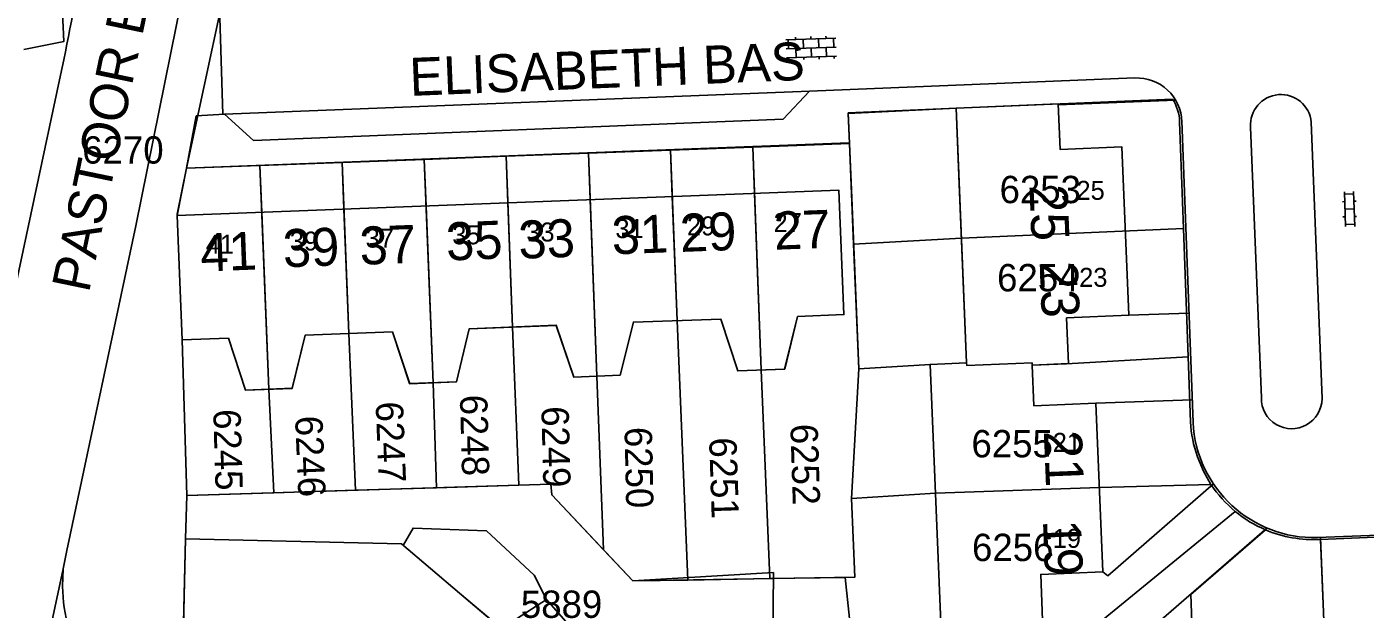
# Model space of a CAD drawing. Extents: x 148816 to 151297, y 399515 to 402500.
# Drawn here: x 150122.1 to 150210.2, y 399895.9 to 399934.3 of the extents above; entities that cross this region are included whole.
import ezdxf

# ---------------------------------------------------------------- set-up
doc = ezdxf.new("R2010")
doc.units = 0
for name, color, linetype in [('B01 Hoofdgebouw  [D] Norm', 7, 'Continuous'), ('B01 Hoofdgebouw  [T] Norm', 7, 'Continuous'), ('B01 hoofgebouw', 7, 'Continuous'), ('B07 Tussenmuur  [D] Norm', 7, 'Continuous'), ('G01 perceelsgrens', 7, 'Continuous'), ('S02 Open verharding  Norm', 7, 'Continuous'), ('T01 Muur  [T] Gem', 7, 'Continuous'), ('T04 Haag heg  [D] Gem', 7, 'Continuous'), ('V00 Kant verharding algemeen  [T] Norm', 7, 'Continuous'), ('V00 Kant verharding algemeen secundair  [T] Gem', 7, 'Continuous'), ('Z01 perceelnummer', 7, 'Continuous'), ('Z02 huisnummer', 7, 'Continuous'), ('Z02 Huisnummer  [Tekst] Norm', 7, 'Continuous'), ('Z06 straatnaam', 7, 'Continuous')]:
    doc.layers.add(name, color=color, linetype=linetype)

msp = doc.modelspace()

# ---------------------------------------------------------------- linework, layer by layer
at = {"layer": 'B01 Hoofdgebouw  [D] Norm'}
for p, q in [((150183.96, 399912.15), (150183.966, 399911.981)), ((150183.966, 399911.981), (150188.264, 399912.148)), ((150188.264, 399912.148), (150188.273, 399911.998)), ((150162.01, 399897.79), (150171.252, 399898.342)), ((150171.252, 399898.342), (150171.219, 399893.637))]:
    msp.add_line(p, q, dxfattribs=at)
msp.add_lwpolyline([(150150.6, 399896.99), (150153.353, 399894.649), (150156.332, 399896.578), (150158.387, 399894.21)], dxfattribs=at)
at = {"layer": 'B01 Hoofdgebouw  [T] Norm'}
for p, q in [((150189.977, 399929.201), (150183.275, 399928.921)), ((150183.275, 399928.921), (150183.955, 399912.147)), ((150190.106, 399926.201), (150189.977, 399929.201)), ((150194.177, 399926.366), (150190.106, 399926.201)), ((150194.177, 399926.366), (150194.622, 399915.28)), ((150132.028, 399921.849), (150175.555, 399923.514)), ((150175.555, 399923.514), (150175.889, 399915.323)), ((150132.028, 399921.849), (150132.362, 399913.658)), ((150172.841, 399915.211), (150171.988, 399911.738)), ((150175.889, 399915.323), (150172.841, 399915.211)), ((150194.622, 399915.28), (150190.539, 399915.105)), ((150190.539, 399915.105), (150190.66, 399912.1)), ((150168.901, 399911.62), (150171.988, 399911.738)), ((150183.955, 399912.147), (150181.559, 399912.051)), ((150181.559, 399912.051), (150182.265, 399895.028)), ((150190.66, 399912.1), (150188.273, 399911.998)), ((150188.273, 399911.998), (150188.381, 399909.325)), ((150158.115, 399911.214), (150161.18, 399911.338)), ((150188.381, 399909.325), (150192.468, 399909.49)), ((150192.468, 399909.49), (150192.916, 399898.386)), ((150156.61, 399904.16), (150132.66, 399903.41)), ((150156.67, 399903.46), (150156.61, 399904.16)), ((150162.01, 399897.79), (150156.67, 399903.46)), ((150132.36, 399891.36), (150132.58, 399900.56)), ((150132.58, 399900.56), (150146.79, 399900.23)), ((150146.79, 399900.23), (150150.6, 399896.99)), ((150188.829, 399898.221), (150192.916, 399898.386)), ((150188.951, 399895.211), (150188.829, 399898.221))]:
    msp.add_line(p, q, dxfattribs=at)
for points in [[(150176.174, 399928.622), (150183.282, 399928.928)], [(150158.115, 399911.214), (150156.966, 399914.621), (150151.238, 399914.399), (150150.399, 399910.903)], [(150168.901, 399911.62), (150167.786, 399915.032), (150162.043, 399914.832), (150161.18, 399911.338)], [(150132.362, 399913.658), (150135.396, 399913.771), (150136.515, 399910.355), (150139.595, 399910.474)], [(150146.188, 399914.186), (150140.449, 399913.969), (150139.595, 399910.474)], [(150146.188, 399914.186), (150147.324, 399910.775), (150150.399, 399910.903)]]:
    msp.add_lwpolyline(points, dxfattribs=at)
at = {"layer": 'B01 hoofgebouw'}
for points in [[(150183.477, 399923.926), (150183.275, 399928.921), (150189.977, 399929.201), (150190.106, 399926.201), (150194.177, 399926.366), (150194.622, 399915.28), (150190.539, 399915.105), (150190.66, 399912.1), (150188.273, 399911.998), (150188.381, 399909.325), (150192.468, 399909.49), (150192.916, 399898.386), (150188.829, 399898.221), (150188.951, 399895.211), (150183.31, 399894.982), (150183.436, 399891.87), (150184.179, 399891.87), (150184.526, 399882.723), (150179.53, 399882.533)], [(150135.396, 399913.771), (150132.362, 399913.658), (150132.028, 399921.849), (150175.555, 399923.514), (150175.889, 399915.323), (150172.841, 399915.211)], [(150183.477, 399923.926), (150183.96, 399912.15), (150181.56, 399912.05), (150182.27, 399895.03), (150176.73, 399894.8), (150176.86, 399891.6)], [(150135.4, 399913.77), (150136.52, 399910.36), (150139.6, 399910.47), (150140.45, 399913.97), (150146.19, 399914.19), (150147.32, 399910.78), (150150.4, 399910.9), (150151.24, 399914.4), (150156.97, 399914.62), (150158.12, 399911.21), (150161.18, 399911.34), (150162.04, 399914.83), (150167.79, 399915.03), (150168.9, 399911.62), (150171.99, 399911.74), (150172.84, 399915.21)], [(150177.38, 399858.38), (150174.27, 399854.46), (150157.39, 399867.87), (150146.1, 399877.88), (150146.2, 399877.97), (150141.11, 399882.58), (150141.04, 399882.49), (150134.15, 399888.76), (150134.23, 399888.84), (150132.93, 399889.99), (150132.82, 399889.97), (150132.27, 399891.31), (150132.36, 399891.36), (150132.58, 399900.56), (150146.79, 399900.23), (150150.6, 399896.99)], [(150150.6, 399896.99), (150152.767, 399895.147)]]:
    msp.add_lwpolyline(points, dxfattribs=at)
at = {"layer": 'B07 Tussenmuur  [D] Norm'}
for p, q in [((150170.451, 399911.68), (150170.003, 399923.302)), ((150170.451, 399911.68), (150170.003, 399923.302)), ((150143.312, 399914.08), (150142.993, 399922.268)), ((150143.312, 399914.08), (150142.993, 399922.268)), ((150148.861, 399910.84), (150148.399, 399922.475)), ((150148.861, 399910.84), (150148.399, 399922.475)), ((150154.092, 399914.51), (150153.785, 399922.681)), ((150154.092, 399914.51), (150153.785, 399922.681)), ((150159.641, 399911.275), (150159.2, 399922.888)), ((150159.641, 399911.275), (150159.2, 399922.888)), ((150164.912, 399914.93), (150164.597, 399923.095)), ((150164.912, 399914.93), (150164.597, 399923.095)), ((150137.597, 399922.062), (150138.061, 399910.415)), ((150137.597, 399922.062), (150138.061, 399910.415)), ((150183.627, 399920.357), (150198.227, 399920.989)), ((150183.627, 399920.357), (150198.227, 399920.989)), ((150181.913, 399903.577), (150192.695, 399903.935)), ((150181.913, 399903.577), (150192.695, 399903.935))]:
    msp.add_line(p, q, dxfattribs=at)
at = {"layer": 'G01 perceelsgrens'}
for points in [[(150120.655, 399953.937), (150123.589, 399954.459), (150124.564, 399933.301), (150121.954, 399932.791)], [(150132.645, 399924.965), (150136.128, 399941.229)], [(150197.5, 399929.52), (150183.28, 399928.92), (150176.174, 399928.576), (150176.255, 399926.588)], [(150197.97, 399928.03), (150198.227, 399920.989)], [(150153.669, 399925.748), (150159.084, 399925.949)], [(150159.084, 399925.949), (150164.48, 399926.15)], [(150159.084, 399925.949), (150159.641, 399911.275), (150160.073, 399899.847)], [(150164.48, 399926.15), (150169.886, 399926.351)], [(150164.48, 399926.15), (150164.912, 399914.93), (150165.612, 399897.85)], [(150169.886, 399926.351), (150176.255, 399926.588)], [(150169.886, 399926.351), (150170.451, 399911.68), (150171.012, 399897.941)], [(150176.255, 399926.588), (150176.526, 399919.963)], [(150132.645, 399924.965), (150132.03, 399921.85), (150132.36, 399913.66), (150132.66, 399903.41)], [(150132.645, 399924.965), (150137.474, 399925.145)], [(150137.474, 399925.145), (150142.873, 399925.346)], [(150137.474, 399925.145), (150138.061, 399910.415), (150138.379, 399903.589)], [(150142.873, 399925.346), (150148.276, 399925.547)], [(150142.873, 399925.346), (150143.312, 399914.08), (150143.75, 399903.757)], [(150148.276, 399925.547), (150153.669, 399925.748)], [(150148.276, 399925.547), (150148.861, 399910.84), (150149.097, 399903.925)], [(150153.669, 399925.748), (150154.092, 399914.51), (150154.512, 399904.094)], [(150176.526, 399919.963), (150183.627, 399920.357), (150198.227, 399920.989)], [(150198.227, 399920.989), (150198.535, 399912.54)], [(150176.526, 399919.963), (150176.861, 399911.747)], [(150176.387, 399903.217), (150176.861, 399911.747)], [(150176.861, 399911.747), (150181.56, 399912.05), (150183.96, 399912.15), (150183.966, 399911.981), (150188.264, 399912.148), (150188.27, 399912), (150190.53, 399912.095), (150198.535, 399912.54)], [(150198.535, 399912.54), (150198.69, 399908.27)], [(150199.14, 399905.96), (150199.531, 399905.029), (150200.03, 399904.15)], [(150138.379, 399903.589), (150143.75, 399903.757)], [(150143.75, 399903.757), (150149.097, 399903.925)], [(150149.097, 399903.925), (150154.512, 399904.094)], [(150154.512, 399904.094), (150156.61, 399904.16), (150156.67, 399903.46), (150160.073, 399899.847)], [(150176.387, 399903.217), (150181.913, 399903.577), (150192.695, 399903.935), (150200.03, 399904.15)], [(150132.733, 399886.712), (150132.249, 399889.719), (150132.27, 399891.31), (150132.36, 399891.36), (150132.58, 399900.56), (150132.66, 399903.41)], [(150132.66, 399903.41), (150138.379, 399903.589)], [(150175.974, 399898.024), (150176.598, 399898.034), (150176.387, 399903.217)], [(150186.615, 399891.991), (150189.075, 399892.085), (150201.63, 399902.37)], [(150203.61, 399901.16), (150198.7, 399896.9), (150198.98, 399889.6), (150198.833, 399889.594), (150199.14, 399882.667), (150199.27, 399882.672), (150199.741, 399875.307)], [(150207.23, 399900.53), (150215.939, 399900.891)], [(150207.23, 399900.53), (150207.43, 399895.74), (150207.66, 399889.95), (150207.513, 399889.944), (150207.73, 399886.12), (150208.153, 399876.029)], [(150160.073, 399899.847), (150162.01, 399897.79), (150165.612, 399897.85)], [(150165.612, 399897.85), (150171.012, 399897.941)], [(150171.012, 399897.941), (150175.974, 399898.024)], [(150175.974, 399898.024), (150176.64, 399891.577)]]:
    msp.add_lwpolyline(points, dxfattribs=at)
for centre, radius, start, end in [((150195.088, 399927.94), 2.883, 1.78531, 33.22901), ((150206.82, 399908.655), 8.139, 182.71091, 199.33601), ((150207.012, 399908.817), 8.398, 213.75912, 230.14413), ((150206.716, 399908.467), 7.939, 230.16732, 246.97355), ((150206.746, 399908.465), 7.95, 246.76551, 273.48952)]:
    msp.add_arc(centre, radius, start, end, dxfattribs=at)
at = {"layer": 'S02 Open verharding  Norm'}
for p, q in [((150172.061, 399933.428), (150175.359, 399933.539)), ((150172.081, 399932.829), (150175.379, 399932.939)), ((150172.211, 399933.433), (150172.231, 399932.834)), ((150172.71, 399933.45), (150172.705, 399933.6)), ((150172.731, 399932.85), (150172.751, 399932.251)), ((150173.21, 399933.467), (150173.23, 399932.867)), ((150173.71, 399933.484), (150173.705, 399933.634)), ((150173.73, 399932.884), (150173.75, 399932.284)), ((150174.21, 399933.5), (150174.23, 399932.901)), ((150174.709, 399933.517), (150174.704, 399933.667)), ((150174.75, 399932.318), (150174.729, 399932.918)), ((150175.209, 399933.534), (150175.229, 399932.934)), ((150172.101, 399932.229), (150175.399, 399932.34)), ((150172.251, 399932.234), (150172.256, 399932.084)), ((150173.25, 399932.268), (150173.255, 399932.118)), ((150174.25, 399932.301), (150174.255, 399932.151)), ((150175.249, 399932.335), (150175.254, 399932.185)), ((150208.809, 399923.415), (150208.886, 399921.117)), ((150208.814, 399923.265), (150209.413, 399923.285)), ((150209.408, 399923.435), (150209.485, 399921.137)), ((150208.83, 399922.766), (150208.68, 399922.761)), ((150209.447, 399922.286), (150208.847, 399922.266)), ((150209.58, 399922.791), (150209.43, 399922.786)), ((150208.864, 399921.766), (150208.714, 399921.761)), ((150209.614, 399921.791), (150209.464, 399921.786)), ((150208.881, 399921.267), (150209.48, 399921.287))]:
    msp.add_line(p, q, dxfattribs=at)
at = {"layer": 'T01 Muur  [T] Gem'}
msp.add_line((150176.392, 399923.55), (150176.174, 399928.622), dxfattribs=at)
at = {"layer": 'T04 Haag heg  [D] Gem'}
for p, q in [((150159.2, 399922.888), (150159.084, 399925.949)), ((150164.598, 399923.095), (150164.48, 399926.15)), ((150170.003, 399923.302), (150169.886, 399926.351)), ((150137.597, 399922.062), (150137.474, 399925.145)), ((150142.993, 399922.268), (150142.873, 399925.346)), ((150148.398, 399922.475), (150148.276, 399925.547)), ((150153.784, 399922.681), (150153.669, 399925.748)), ((150176.392, 399923.55), (150176.861, 399911.747)), ((150176.526, 399919.963), (150183.627, 399920.357)), ((150154.512, 399904.094), (150154.092, 399914.51)), ((150165.612, 399897.85), (150164.912, 399914.93)), ((150132.362, 399913.658), (150132.66, 399903.41)), ((150143.75, 399903.757), (150143.312, 399914.08)), ((150171.012, 399897.941), (150170.451, 399911.68)), ((150176.861, 399911.747), (150176.387, 399903.217)), ((150176.861, 399911.747), (150181.559, 399912.051)), ((150149.097, 399903.925), (150148.861, 399910.84)), ((150160.073, 399899.847), (150159.641, 399911.275)), ((150138.379, 399903.589), (150138.061, 399910.415)), ((150156.67, 399903.46), (150156.61, 399904.16)), ((150162.01, 399897.79), (150156.67, 399903.46)), ((150176.387, 399903.217), (150181.913, 399903.577)), ((150176.387, 399903.217), (150176.598, 399898.034)), ((150176.598, 399898.034), (150162.01, 399897.79))]:
    msp.add_line(p, q, dxfattribs=at)
at = {"layer": 'V00 Kant verharding algemeen  [T] Norm'}
for p, q in [((150129.31, 399921.18), (150132.36, 399936.29)), ((150118.49, 399903.59), (150124.359, 399931.1)), ((150173.623, 399930.041), (150195.024, 399930.906)), ((150197.709, 399929.449), (150189.98, 399929.142)), ((150133.271, 399928.414), (150132.644, 399924.972)), ((150198.113, 399928.086), (150198.853, 399908.23)), ((150132.03, 399921.939), (150132.028, 399921.849)), ((150124.78, 399899.79), (150129.31, 399921.18)), ((150198.585, 399915.428), (150194.622, 399915.28)), ((150198.797, 399909.726), (150192.468, 399909.49)), ((150193.255, 399898.119), (150200.194, 399904.182)), ((150269.178, 399903.158), (150207.042, 399900.645)), ((150203.706, 399901.276), (150193.163, 399892.132)), ((150207.229, 399900.653), (150207.428, 399895.743)), ((150124.54, 399898.58), (150124.78, 399899.79)), ((150124.491, 399897.43), (150124.54, 399898.58)), ((150192.916, 399898.386), (150193.255, 399898.119))]:
    msp.add_line(p, q, dxfattribs=at)
for points in [[(150133.271, 399928.414), (150135.148, 399928.521), (150137.055, 399926.8), (150171.887, 399928.195), (150173.623, 399930.041)], [(150203.346, 399909.847), (150202.632, 399927.674)], [(150206.626, 399927.999), (150207.341, 399909.792)], [(150176.214, 399926.626), (150132.644, 399924.972), (150132.03, 399921.939)], [(150146.91, 399900.174), (150147.547, 399901.267), (150152.375, 399901.083), (150155.522, 399898.181), (150156.332, 399896.578)]]:
    msp.add_lwpolyline(points, dxfattribs=at)
for centre, radius, start, end in [((149964.146, 399965.18), 163.798, 347.99127, 353.77892), ((150195.159, 399927.952), 2.957, 1.42056, 92.60729), ((150204.631, 399927.813), 2.004, 5.32927, 183.97477), ((150205.343, 399909.813), 1.998, 179.02518, 359.3977), ((150206.825, 399908.623), 7.981, 182.8256, 271.56006), ((150134.293, 399897.534), 9.803, 180.60549, 213.30997)]:
    msp.add_arc(centre, radius, start, end, dxfattribs=at)
at = {"layer": 'V00 Kant verharding algemeen secundair  [T] Gem'}
for p, q in [((150134.83, 399934.888), (150135.041, 399928.498)), ((150135.148, 399928.521), (150173.623, 399930.041))]:
    msp.add_line(p, q, dxfattribs=at)
msp.add_lwpolyline([(150124.54, 399898.58), (150120.43, 399879.41)], dxfattribs=at)

# ---------------------------------------------------------------- texts
at = {"layer": 'Z01 perceelnummer'}
for s, p in [('6270', (150125.786, 399925.269)), ('6253', (150186.125, 399922.664)), ('6254', (150185.963, 399916.858)), ('6255', (150184.277, 399905.929)), ('6256', (150184.313, 399899.099)), ('5889', (150154.636, 399895.358))]:
    msp.add_text(s, height=1.8, dxfattribs=at).set_placement(p)
for s, rotation, p in [('6248', 271.53434, (150150.627, 399910.03)), ('6247', 272.17837, (150145.085, 399909.574)), ('6249', 271.47754, (150155.981, 399909.275)), ('6245', 271.66111, (150134.4, 399909.08)), ('6246', 272.40261, (150139.782, 399908.633)), ('6250', 271.19705, (150161.455, 399907.913)), ('6252', 271.82373, (150172.36, 399908.109)), ('6251', 271.87881, (150167.017, 399907.217))]:
    msp.add_text(s, height=1.8, rotation=rotation, dxfattribs=at).set_placement(p)
at = {"layer": 'Z02 huisnummer'}
for s, rotation, p in [('25', 272.2929, (150188.085, 399923.849)), ('35', 2.17837, (150149.757, 399918.885)), ('33', 2.17837, (150154.519, 399918.998)), ('31', 2.17837, (150160.657, 399919.288)), ('29', 2.17837, (150165.139, 399919.449)), ('27', 2.17837, (150171.328, 399919.595)), ('41', 2.17837, (150133.599, 399918.157)), ('39', 2.17837, (150139.024, 399918.434)), ('37', 2.17837, (150144.073, 399918.603)), ('23', 272.2929, (150188.761, 399918.794)), ('21', 272.2929, (150189.034, 399907.658)), ('19', 272.2929, (150188.976, 399901.777))]:
    msp.add_text(s, height=2.5, rotation=rotation, dxfattribs=at).set_placement(p)
at = {"layer": 'Z02 Huisnummer  [Tekst] Norm'}
for s, p in [('25', (150191.183, 399922.883)), ('33', (150154.995, 399920.14)), ('31', (150160.856, 399920.364)), ('29', (150165.564, 399920.544)), ('27', (150171.26, 399920.762)), ('41', (150133.911, 399919.335)), ('39', (150139.437, 399919.545)), ('37', (150144.426, 399919.736)), ('35', (150150.123, 399919.954)), ('23', (150191.363, 399917.155)), ('21', (150189.624, 399906.288)), ('19', (150189.624, 399899.97))]:
    msp.add_text(s, height=1.25, dxfattribs=at).set_placement(p)
at = {"layer": 'Z06 straatnaam'}
for s, rotation, p in [('PASTOOR ERASSTRAAT', 78.28547, (150126.22, 399916.707)), ('ELISABETH BAS', 2.35016, (150147.36, 399929.722))]:
    msp.add_text(s, height=2.5, rotation=rotation, dxfattribs=at).set_placement(p)

doc.saveas('drawing.dxf')
